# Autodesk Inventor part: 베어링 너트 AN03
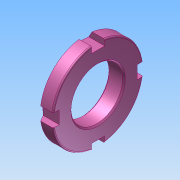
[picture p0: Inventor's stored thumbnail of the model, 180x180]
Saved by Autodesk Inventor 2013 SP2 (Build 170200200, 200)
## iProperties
Created: 2025-05
Part Number: 베어링 너트 AN03
Material: Generic
Document SubType Name: Modeling
Designer: a
Density: 1 g/cm^3
Author: a
변환 표준: STEP AP214IS
전처리기: Build: 200, Release: 2013 SP2 Update 6 - Date: Thu 07/17/2014
전송 단위: 밀리미터
불확실성: 0.01
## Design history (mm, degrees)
node "베어링 너트 AN031"
body "Solid1"
node "기준1"
